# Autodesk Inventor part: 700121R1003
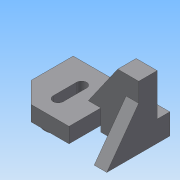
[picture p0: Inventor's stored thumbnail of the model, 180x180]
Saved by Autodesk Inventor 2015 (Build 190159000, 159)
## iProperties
Created: 2020-01
Part Number: 700121R1003
Material: 일반
Document SubType Name: Modeling
Designer: H10
Density: 1 g/cm^3
Appearance: 기본값
Author: H10
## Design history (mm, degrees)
sketch "스케치1"
  geometry: L1 (-35, 53)-(80, 53); L2 (80, 53)-(80, 16); L3 (35, -22)-(-10, -22); L4 (-35, 3)-(-35, 53); L5 (35, -22)-(35, 16); L6 (35, 16)-(80, 16); L7 (80, 16)-(65, 16); L8 (65, 16)-(65, -22); L9 (65, -22)-(80, -22); L10 (80, -22)-(80, 16); L11 (0, 28)-(0, 0); L12 (-6, 28)-(-6, 0); L13 (6, 0)-(6, 28); L14 (-35, 3)-(-10, -22); C1 r 16 at (0, 0); C2 r 10 at (0, 0); A1 r 6 centre (0, 28) between (6, 28) and (-6, 28); A2 r 6 centre (0, 0) between (-6, 0) and (6, 0); 2 further points
  constraints: 30 end point, 5 parallel, 4 centre point, 4 point on circle, 4 tangent, 3 coincident, 3 horizontal, 2 perpendicular, 1 midpoint, 1 vertical
  dimensions: "d0" = 16 radius of C1; "d1" = 10 radius of C2; "d2" = 38 distance of L3.start L5.end; "d3" = 35 distance from line of L4 point (0, 0); "d4" = 53 distance from line of L1 point (0, 0); "d6" = 45 distance of L2.end L5.end; "d7" = 115 distance of L1.start L1.end; "d8" = 38 distance between parallel lines of L3 L6; "d9" = 38 distance between parallel lines of L9 L6; "d10" = 15 distance between parallel lines of L10 L8; "d11" = 28 distance of L11.start L11.end; "d12" = 6 radius of A1; "d13" = 75 distance between parallel lines of L3 L1; "d14" = 25 horizontal distance of L4.start L3.end; "d15" = 45 deg angle of L14 L3
extrude "돌출1" new body sketch "스케치1" distance "d16" = 60; taper "d17" = 0 deg
sketch "스케치2"
  geometry: L1 (0, 0)-(-52.303, 38); L2 (0, 38)-(-60, 38) reference; L3 (-60, 38)-(-60, 0); L4 (-60, 0)-(0, 0); L5 (0, 38)-(0, 0) reference; 1 further point
  constraints: 6 end point, 1 perpendicular, 1 point on line, 1 vertical
  dimensions: "d18" = 144 deg angle of L1 L2
extrude "돌출2" cut sketch "스케치2" stored distance "d19" = 60; taper "d20" = 0 deg
extrude "돌출3" join sketch "스케치1" distance "d21" = 25; taper "d22" = 0 deg
sketch "스케치3"
  geometry: L1 (-25, 7)-(45, 7); L2 (45, 7)-(45, 0); L3 (45, 0)-(-25, 0); L4 (-25, 0)-(-25, 7); 2 further points
  constraints: 8 end point, 2 parallel, 1 coincident, 1 horizontal, 1 perpendicular
  dimensions: "d23" = 7 distance of L3.end L1.start; "d24" = 70 distance of L1.start L1.end
extrude "돌출4" cut sketch "스케치3" stored distance "d25" = 25; taper "d26" = 0 deg
extrude "돌출5" join sketch "스케치1" distance "d27" = 7; taper "d28" = 0 deg
sketch "스케치4"
  geometry: L1 (-6, 28)-(-6, 0) reference; L2 (6, 0)-(6, 28) reference; A1 r 6 centre (0, 28) between (6, 28) and (-6, 28) reference; A2 r 6 centre (0, 0) between (-6, 0) and (6, 0) reference; 1 further point
extrude "돌출6" cut sketch "스케치4" distance "d29" = 12; taper "d30" = 0 deg
sketch "스케치5"
  geometry: L1 (45, 0)-(45, 50); L2 (45, 50)-(20, 50); L3 (20, 50)-(-15.01, 0); L4 (-15.01, 0)-(45, 0); 2 further points
  constraints: 8 end point, 2 horizontal, 1 coincident, 1 vertical
  dimensions: "d31" = 25 distance of L1.end L2.end; "d32" = 55 deg angle of L2 L3; "d33" = 50 distance of L1.start L1.end
extrude "돌출7" join sketch "스케치5" distance "d34" = 22; taper "d35" = 0 deg
node "솔리드1"
